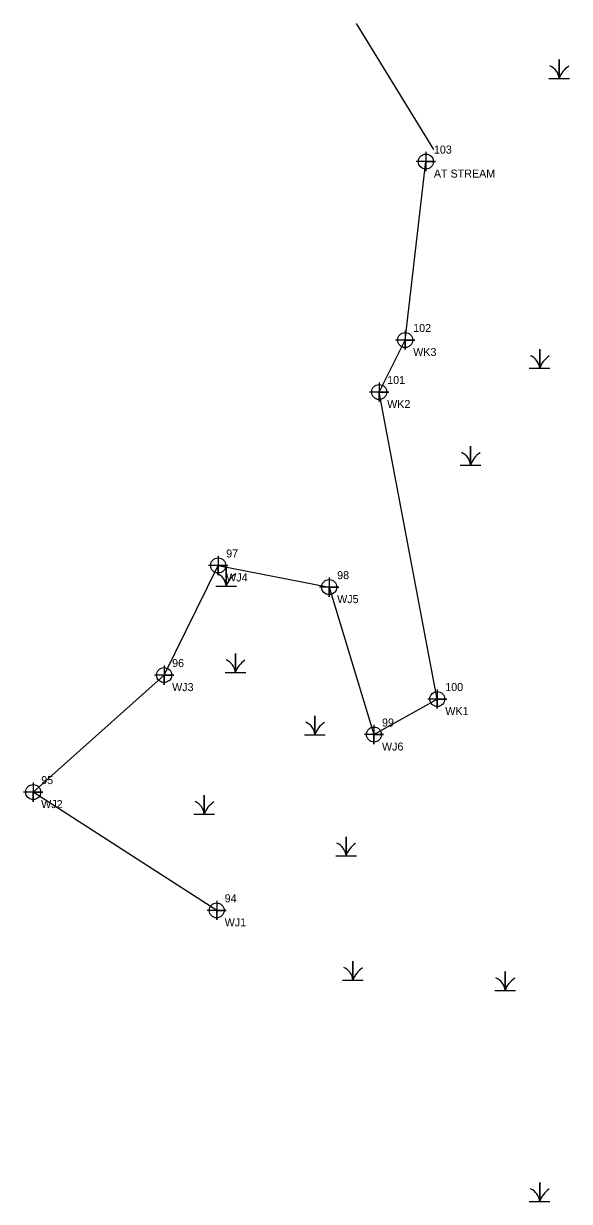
# Model space of a CAD drawing. Extents: x 2189822 to 2191198, y 387253 to 388663.
# Drawn here: x 2190286.1 to 2190456.5, y 387461.5 to 387829.6 of the extents above; entities that cross this region are included whole.
import ezdxf

# ---------------------------------------------------------------- set-up
doc = ezdxf.new("R2010")
doc.units = 0
for name, color, linetype in [('Structure020030_Alleghany', 7, 'Continuous'), ('Structure040008_Ashe', 7, 'Continuous'), ('Structure090007_Brunswick', 7, 'Continuous'), ('Structure620024_Moore', 7, 'Continuous'), ('Structure780124_Rockingham', 7, 'Continuous')]:
    doc.layers.add(name, color=color, linetype=linetype)

msp = doc.modelspace()

# ---------------------------------------------------------------- linework, layer by layer
at = {"layer": 'Structure020030_Alleghany'}
for points in [[(2190411.74, 387789.43), (2190411.74, 387783.43), (2190411.74, 387786.43), (2190414.74, 387786.43), (2190408.74, 387786.43)], [(2190405.27, 387733.67), (2190405.27, 387727.67), (2190405.27, 387730.67), (2190408.27, 387730.67), (2190402.27, 387730.67)], [(2190397.15, 387717.42), (2190397.15, 387711.42), (2190397.15, 387714.42), (2190400.15, 387714.42), (2190394.15, 387714.42)], [(2190346.89, 387663.22), (2190346.89, 387657.22), (2190346.89, 387660.22), (2190349.89, 387660.22), (2190343.89, 387660.22)], [(2190381.54, 387656.46), (2190381.54, 387650.46), (2190381.54, 387653.46), (2190384.54, 387653.46), (2190378.54, 387653.46)], [(2190330.02, 387628.97), (2190330.02, 387622.97), (2190330.02, 387625.97), (2190333.02, 387625.97), (2190327.02, 387625.97)], [(2190415.3, 387621.48), (2190415.3, 387615.48), (2190415.3, 387618.48), (2190418.3, 387618.48), (2190412.3, 387618.48)], [(2190395.53, 387610.4), (2190395.53, 387604.4), (2190395.53, 387607.4), (2190398.53, 387607.4), (2190392.53, 387607.4)], [(2190289.14, 387592.41), (2190289.14, 387586.41), (2190289.14, 387589.41), (2190292.14, 387589.41), (2190286.14, 387589.41)], [(2190346.43, 387555.46), (2190346.43, 387549.46), (2190346.43, 387552.46), (2190349.43, 387552.46), (2190343.43, 387552.46)]]:
    msp.add_lwpolyline(points, dxfattribs=at)
for centre in [(2190411.74, 387786.43), (2190405.27, 387730.67), (2190397.15, 387714.42), (2190346.89, 387660.22), (2190381.54, 387653.46), (2190330.02, 387625.97), (2190415.3, 387618.48), (2190395.53, 387607.4), (2190289.14, 387589.41), (2190346.43, 387552.46)]:
    msp.add_circle(centre, 2.34, dxfattribs=at)
at = {"layer": 'Structure620024_Moore'}
msp.add_line((2190414.24, 387790.18), (2190390.04, 387829.56), dxfattribs=at)
for points in [[(2190405.27, 387730.67), (2190411.74, 387786.43)], [(2190346.43, 387552.46), (2190289.14, 387589.41), (2190330.02, 387625.97), (2190346.89, 387660.22), (2190381.54, 387653.46), (2190395.53, 387607.4), (2190415.3, 387618.48), (2190397.15, 387714.42), (2190405.27, 387730.67)]]:
    msp.add_lwpolyline(points, dxfattribs=at)
at = {"layer": 'Structure780124_Rockingham'}
for p, q in [((2190453.32, 387815.06), (2190453.32, 387815.06)), ((2190447.26, 387724.52), (2190447.26, 387724.52)), ((2190425.67, 387694.28), (2190425.67, 387694.28)), ((2190349.39, 387656.47), (2190349.39, 387656.47)), ((2190352.25, 387629.46), (2190352.25, 387629.46)), ((2190377.08, 387610.01), (2190377.08, 387610.01)), ((2190342.54, 387585.17), (2190342.54, 387585.17)), ((2190386.8, 387572.2), (2190386.8, 387572.2)), ((2190388.96, 387533.31), (2190388.96, 387533.31)), ((2190436.46, 387530.07), (2190436.46, 387530.07)), ((2190447.26, 387464.17), (2190447.26, 387464.17))]:
    msp.add_line(p, q, dxfattribs=at)
for points in [[(2190450.1, 387812.39), (2190453.32, 387812.39), (2190453.32, 387818.31), (2190453.32, 387812.39), (2190456.55, 387812.39)], [(2190444.03, 387721.85), (2190447.26, 387721.85), (2190447.26, 387727.77), (2190447.26, 387721.85), (2190450.48, 387721.85)], [(2190422.44, 387691.6), (2190425.67, 387691.6), (2190425.67, 387697.52), (2190425.67, 387691.6), (2190428.89, 387691.6)], [(2190346.17, 387653.8), (2190349.39, 387653.8), (2190349.39, 387659.72), (2190349.39, 387653.8), (2190352.62, 387653.8)], [(2190349.03, 387626.78), (2190352.25, 387626.78), (2190352.25, 387632.7), (2190352.25, 387626.78), (2190355.48, 387626.78)], [(2190373.86, 387607.34), (2190377.08, 387607.34), (2190377.08, 387613.26), (2190377.08, 387607.34), (2190380.31, 387607.34)], [(2190339.31, 387582.49), (2190342.54, 387582.49), (2190342.54, 387588.41), (2190342.54, 387582.49), (2190345.76, 387582.49)], [(2190383.58, 387569.53), (2190386.8, 387569.53), (2190386.8, 387575.45), (2190386.8, 387569.53), (2190390.03, 387569.53)], [(2190385.73, 387530.64), (2190388.96, 387530.64), (2190388.96, 387536.55), (2190388.96, 387530.64), (2190392.19, 387530.64)], [(2190433.24, 387527.4), (2190436.46, 387527.4), (2190436.46, 387533.31), (2190436.46, 387527.4), (2190439.69, 387527.4)], [(2190444.03, 387461.5), (2190447.26, 387461.5), (2190447.26, 387467.42), (2190447.26, 387461.5), (2190450.48, 387461.5)]]:
    msp.add_lwpolyline(points, dxfattribs=at)
for centre, radius, start, end in [((2190448.72, 387812.06), 4.61, 4.1403, 67.535), ((2190460.16, 387810.12), 7.21, 122.1274, 161.6222), ((2190442.66, 387721.52), 4.61, 4.1403, 67.535), ((2190454.1, 387719.58), 7.21, 122.1274, 161.6222), ((2190421.07, 387691.27), 4.61, 4.1403, 67.535), ((2190432.51, 387689.33), 7.21, 122.1274, 161.6222), ((2190344.79, 387653.46), 4.61, 4.1403, 67.535), ((2190356.23, 387651.52), 7.21, 122.1274, 161.6222), ((2190347.65, 387626.45), 4.61, 4.1403, 67.535), ((2190359.09, 387624.51), 7.21, 122.1274, 161.6222), ((2190372.48, 387607.01), 4.61, 4.1403, 67.535), ((2190383.93, 387605.07), 7.21, 122.1274, 161.6222), ((2190337.94, 387582.16), 4.61, 4.1403, 67.535), ((2190349.38, 387580.22), 7.21, 122.1274, 161.6222), ((2190382.2, 387569.19), 4.61, 4.1403, 67.535), ((2190393.64, 387567.26), 7.21, 122.1274, 161.6222), ((2190384.36, 387530.3), 4.61, 4.1403, 67.535), ((2190395.8, 387528.36), 7.21, 122.1274, 161.6222), ((2190431.86, 387527.06), 4.61, 4.1403, 67.535), ((2190443.3, 387525.12), 7.21, 122.1274, 161.6222), ((2190442.66, 387461.16), 4.61, 4.1403, 67.535), ((2190454.1, 387459.23), 7.21, 122.1274, 161.6222)]:
    msp.add_arc(centre, radius, start, end, dxfattribs=at)

# ---------------------------------------------------------------- texts
at = {"layer": 'Structure040008_Ashe'}
for s, p in [('103', (2190414.24, 387788.93)), ('102', (2190407.77, 387733.17)), ('101', (2190399.65, 387716.92)), ('97', (2190349.39, 387662.72)), ('98', (2190384.04, 387655.96)), ('96', (2190332.52, 387628.47)), ('100', (2190417.8, 387620.98)), ('99', (2190398.03, 387609.9)), ('95', (2190291.64, 387591.91)), ('94', (2190348.93, 387554.96))]:
    msp.add_text(s, height=2.5, dxfattribs=at).set_placement(p)
at = {"layer": 'Structure090007_Brunswick'}
for s, p in [('AT STREAM', (2190414.24, 387781.43)), ('WK3', (2190407.77, 387725.67)), ('WK2', (2190399.65, 387709.42)), ('WJ4', (2190349.39, 387655.22)), ('WJ5', (2190384.04, 387648.46)), ('WJ3', (2190332.52, 387620.97)), ('WK1', (2190417.8, 387613.48)), ('WJ6', (2190398.03, 387602.4)), ('WJ2', (2190291.64, 387584.41)), ('WJ1', (2190348.93, 387547.46))]:
    msp.add_text(s, height=2.5, dxfattribs=at).set_placement(p)

doc.saveas('drawing.dxf')
